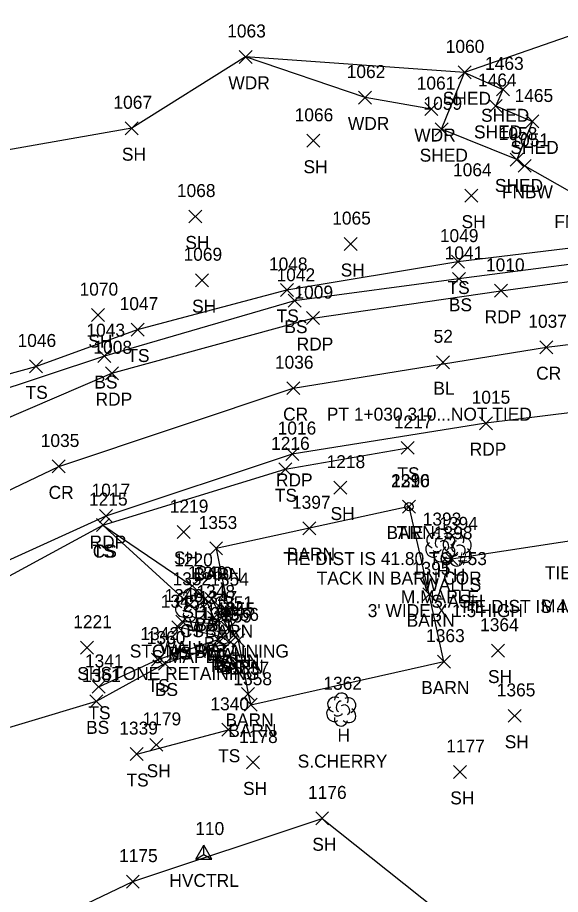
# Model space of a CAD drawing. Extents: x 1526508 to 1531550, y 369926 to 373082.
# Drawn here: x 1530893.3 to 1530976.9, y 370047.9 to 370183.1 of the extents above; entities that cross this region are included whole.
import ezdxf

# ---------------------------------------------------------------- set-up
doc = ezdxf.new("R2010")
doc.units = 0
for name, color, linetype in [('C_A', 7, 'Continuous'), ('C_C', 7, 'Continuous'), ('C_I', 7, 'Continuous'), ('C_TIC', 7, 'Continuous'), ('CBP', 7, 'Continuous'), ('CPSM', 7, 'Continuous'), ('L_A', 7, 'Continuous'), ('L_C', 7, 'Continuous'), ('L_I', 7, 'Continuous'), ('L_TIC', 7, 'Continuous'), ('LAWA', 7, 'Continuous'), ('LBC', 7, 'Continuous'), ('LELB', 7, 'Continuous'), ('LFNC', 7, 'Continuous'), ('LSOGP', 7, 'Continuous'), ('LTD', 7, 'Continuous'), ('LW', 7, 'Continuous'), ('LWS', 7, 'Continuous'), ('P_A', 7, 'Continuous'), ('P_I', 7, 'Continuous'), ('P_TIC', 7, 'Continuous'), ('PET', 7, 'Continuous'), ('PRC', 7, 'Continuous')]:
    doc.layers.add(name, color=color, linetype=linetype)

msp = doc.modelspace()

# ---------------------------------------------------------------- linework, layer by layer
at = {"layer": 'C_TIC'}
for points in [[(1530957.87, 370128.95), (1530959.87, 370130.95)], [(1530959.87, 370128.95), (1530957.87, 370130.95)]]:
    msp.add_lwpolyline(points, dxfattribs=at)
at = {"layer": 'CBP'}
for radius in [0.625, 0.0833]:
    msp.add_circle((1530953.6, 370107.69), radius, dxfattribs=at)
at = {"layer": 'CPSM'}
for p, q in [((1530920.75, 370053.36), (1530922, 370055.53)), ((1530923.25, 370053.36), (1530922, 370055.53)), ((1530922, 370054.08), (1530922, 370055.53)), ((1530920.75, 370053.36), (1530922, 370054.08)), ((1530922, 370054.08), (1530922, 370054.08)), ((1530922, 370054.08), (1530923.25, 370053.36)), ((1530920.75, 370053.36), (1530923.25, 370053.36))]:
    msp.add_line(p, q, dxfattribs=at)
at = {"layer": 'L_TIC'}
for points in [[(1530927.42, 370176.02), (1530929.42, 370178.02)], [(1530929.42, 370176.02), (1530927.42, 370178.02)], [(1530961.18, 370173.64), (1530963.18, 370175.64)], [(1530963.18, 370173.64), (1530961.18, 370175.64)], [(1530967.07, 370171.02), (1530969.07, 370173.02)], [(1530969.07, 370171.02), (1530967.07, 370173.02)], [(1530945.83, 370169.76), (1530947.83, 370171.76)], [(1530947.83, 370169.76), (1530945.83, 370171.76)], [(1530956.06, 370167.98), (1530958.06, 370169.98)], [(1530958.06, 370167.98), (1530956.06, 370169.98)], [(1530965.98, 370168.46), (1530967.98, 370170.46)], [(1530967.98, 370168.46), (1530965.98, 370170.46)], [(1530971.61, 370166.07), (1530973.61, 370168.07)], [(1530973.61, 370166.07), (1530971.61, 370168.07)], [(1530909.89, 370165.02), (1530911.89, 370167.02)], [(1530911.89, 370165.02), (1530909.89, 370167.02)], [(1530957.62, 370164.87), (1530959.62, 370166.87)], [(1530959.62, 370164.87), (1530957.62, 370166.87)], [(1530937.86, 370163.09), (1530939.86, 370165.09)], [(1530939.86, 370163.09), (1530937.86, 370165.09)], [(1530969.21, 370160.2), (1530971.21, 370162.2)], [(1530971.21, 370160.2), (1530969.21, 370162.2)], [(1530970.44, 370159.23), (1530972.44, 370161.23)], [(1530972.44, 370159.23), (1530970.44, 370161.23)], [(1530962.21, 370154.62), (1530964.21, 370156.62)], [(1530964.21, 370154.62), (1530962.21, 370156.62)], [(1530919.67, 370151.42), (1530921.67, 370153.42)], [(1530921.67, 370151.42), (1530919.67, 370153.42)], [(1530943.6, 370147.17), (1530945.6, 370149.17)], [(1530945.6, 370147.17), (1530943.6, 370149.17)], [(1530960.14, 370144.47), (1530962.14, 370146.47)], [(1530962.14, 370144.47), (1530960.14, 370146.47)], [(1530920.7, 370141.6), (1530922.7, 370143.6)], [(1530922.7, 370141.6), (1530920.7, 370143.6)], [(1530960.31, 370141.81), (1530962.31, 370143.81)], [(1530962.31, 370141.81), (1530960.31, 370143.81)], [(1530933.8, 370140.1), (1530935.8, 370142.1)], [(1530935.8, 370140.1), (1530933.8, 370142.1)], [(1530934.97, 370138.44), (1530936.97, 370140.44)], [(1530936.97, 370138.44), (1530934.97, 370140.44)], [(1530904.71, 370136.22), (1530906.71, 370138.22)], [(1530906.71, 370136.22), (1530904.71, 370138.22)], [(1530910.8, 370133.99), (1530912.8, 370135.99)], [(1530912.8, 370133.99), (1530910.8, 370135.99)], [(1530905.69, 370129.9), (1530907.69, 370131.9)], [(1530907.69, 370129.9), (1530905.69, 370131.9)], [(1530895.12, 370128.31), (1530897.12, 370130.31)], [(1530897.12, 370128.31), (1530895.12, 370130.31)], [(1530952.41, 370115.76), (1530954.41, 370117.76)], [(1530954.41, 370115.76), (1530952.41, 370117.76)], [(1530933.55, 370112.45), (1530935.55, 370114.45)], [(1530935.55, 370112.45), (1530933.55, 370114.45)], [(1530942.04, 370109.63), (1530944.04, 370111.63)], [(1530944.04, 370109.63), (1530942.04, 370111.63)], [(1530952.62, 370106.71), (1530954.62, 370108.71)], [(1530954.62, 370106.71), (1530952.62, 370108.71)], [(1530905.44, 370103.85), (1530907.44, 370105.85)], [(1530907.44, 370103.85), (1530905.44, 370105.85)], [(1530905.44, 370103.85), (1530907.44, 370105.85)], [(1530907.44, 370103.85), (1530905.44, 370105.85)], [(1530937.27, 370103.37), (1530939.27, 370105.37)], [(1530939.27, 370103.37), (1530937.27, 370105.37)], [(1530917.89, 370102.78), (1530919.89, 370104.78)], [(1530919.89, 370102.78), (1530917.89, 370104.78)], [(1530922.9, 370100.25), (1530924.9, 370102.25)], [(1530924.9, 370100.25), (1530922.9, 370102.25)], [(1530959.13, 370098.67), (1530961.13, 370100.67)], [(1530961.13, 370098.67), (1530959.13, 370100.67)], [(1530919.21, 370094.49), (1530921.21, 370096.49)], [(1530921.21, 370094.49), (1530919.21, 370096.49)], [(1530921.25, 370092.52), (1530923.25, 370094.52)], [(1530923.25, 370092.52), (1530921.25, 370094.52)], [(1530922.2, 370092.44), (1530924.2, 370094.44)], [(1530924.2, 370092.44), (1530922.2, 370094.44)], [(1530955.74, 370093.19), (1530957.74, 370095.19)], [(1530957.74, 370093.19), (1530955.74, 370095.19)], [(1530918.87, 370091.58), (1530920.87, 370093.58)], [(1530920.87, 370091.58), (1530918.87, 370093.58)], [(1530924.67, 370091.52), (1530926.67, 370093.52)], [(1530926.67, 370091.52), (1530924.67, 370093.52)], [(1530922.55, 370089.61), (1530924.55, 370091.61)], [(1530924.55, 370089.61), (1530922.55, 370091.61)], [(1530917.06, 370088.11), (1530919.06, 370090.11)], [(1530919.06, 370088.11), (1530917.06, 370090.11)], [(1530917.69, 370088.99), (1530919.69, 370090.99)], [(1530919.69, 370088.99), (1530917.69, 370090.99)], [(1530922.86, 370088.69), (1530924.86, 370090.69)], [(1530924.86, 370088.69), (1530922.86, 370090.69)], [(1530924.77, 370087.89), (1530926.77, 370089.89)], [(1530926.77, 370087.89), (1530924.77, 370089.89)], [(1530925.63, 370086.93), (1530927.63, 370088.93)], [(1530927.63, 370086.93), (1530925.63, 370088.93)], [(1530923.22, 370086.21), (1530925.22, 370088.21)], [(1530925.22, 370086.21), (1530923.22, 370088.21)], [(1530924.06, 370086.54), (1530926.06, 370088.54)], [(1530926.06, 370086.54), (1530924.06, 370088.54)], [(1530925.15, 370085.84), (1530927.15, 370087.84)], [(1530927.15, 370085.84), (1530925.15, 370087.84)], [(1530926.29, 370086.09), (1530928.29, 370088.09)], [(1530928.29, 370086.09), (1530926.29, 370088.09)], [(1530903, 370084.96), (1530905, 370086.96)], [(1530905, 370084.96), (1530903, 370086.96)], [(1530966.3, 370084.5), (1530968.3, 370086.5)], [(1530968.3, 370084.5), (1530966.3, 370086.5)], [(1530913.91, 370083.12), (1530915.91, 370085.12)], [(1530915.91, 370083.12), (1530913.91, 370085.12)], [(1530957.98, 370082.81), (1530959.98, 370084.81)], [(1530959.98, 370082.81), (1530957.98, 370084.81)], [(1530915.02, 370082.51), (1530917.02, 370084.51)], [(1530917.02, 370082.51), (1530915.02, 370084.51)], [(1530904.8, 370078.92), (1530906.8, 370080.92)], [(1530906.8, 370078.92), (1530904.8, 370080.92)], [(1530927.82, 370077.82), (1530929.82, 370079.82)], [(1530929.82, 370077.82), (1530927.82, 370079.82)], [(1530904.42, 370076.67), (1530906.42, 370078.67)], [(1530906.42, 370076.67), (1530904.42, 370078.67)], [(1530928.24, 370076.17), (1530930.24, 370078.17)], [(1530930.24, 370076.17), (1530928.24, 370078.17)], [(1530968.87, 370074.45), (1530970.87, 370076.45)], [(1530970.87, 370074.45), (1530968.87, 370076.45)], [(1530924.79, 370072.3), (1530926.79, 370074.3)], [(1530926.79, 370072.3), (1530924.79, 370074.3)], [(1530913.7, 370069.98), (1530915.7, 370071.98)], [(1530915.7, 370069.98), (1530913.7, 370071.98)], [(1530910.67, 370068.56), (1530912.67, 370070.56)], [(1530912.67, 370068.56), (1530910.67, 370070.56)], [(1530928.55, 370067.26), (1530930.55, 370069.26)], [(1530930.55, 370067.26), (1530928.55, 370069.26)], [(1530960.47, 370065.8), (1530962.47, 370067.8)], [(1530962.47, 370065.8), (1530960.47, 370067.8)], [(1530939.23, 370058.65), (1530941.23, 370060.65)], [(1530941.23, 370058.65), (1530939.23, 370060.65)], [(1530910.06, 370048.9), (1530912.06, 370050.9)], [(1530912.06, 370048.9), (1530910.06, 370050.9)]]:
    msp.add_lwpolyline(points, dxfattribs=at)
at = {"layer": 'LAWA'}
msp.add_lwpolyline([(1530957.06, 370168.98), (1530946.83, 370170.76), (1530928.42, 370177.02)], dxfattribs=at)
at = {"layer": 'LBC'}
for points in [[(1530970.21, 370161.2), (1530958.62, 370165.87), (1530962.18, 370174.64), (1530968.07, 370172.02), (1530966.98, 370169.46), (1530972.61, 370167.07)], [(1530972.61, 370167.07), (1530970.21, 370161.2)], [(1530956.74, 370094.19), (1530953.62, 370107.71), (1530938.27, 370104.37)], [(1530938.27, 370104.37), (1530923.9, 370101.25)], [(1530923.9, 370101.25), (1530925.67, 370092.52), (1530926.63, 370087.93), (1530927.29, 370087.09), (1530928.82, 370078.82), (1530929.24, 370077.17), (1530958.98, 370083.81)], [(1530958.98, 370083.81), (1530956.74, 370094.19)]]:
    msp.add_lwpolyline(points, dxfattribs=at)
at = {"layer": 'LELB'}
for points in [[(1530883.54, 370125.84), (1530896.12, 370129.31), (1530911.8, 370134.99), (1530934.8, 370141.1), (1530961.14, 370145.47), (1530991.24, 370149.13)], [(1530991.34, 370146.7), (1530961.31, 370142.81), (1530935.97, 370139.44), (1530906.69, 370130.9), (1530888.23, 370124.76)], [(1530685.88, 369975.28), (1530717.44, 369995.35), (1530750.55, 370015.24), (1530789.81, 370037.94), (1530822.42, 370057.69), (1530849.78, 370074.39), (1530878.97, 370089.95), (1530906.44, 370104.85), (1530934.55, 370113.45), (1530953.41, 370116.76)], [(1530906.44, 370104.85), (1530919.87, 370092.58)], [(1530906.44, 370104.85), (1530920.21, 370095.49)], [(1530923.55, 370090.61), (1530922.25, 370093.52)], [(1530925.06, 370087.54), (1530918.06, 370089.11)], [(1530926.15, 370086.84), (1530916.02, 370083.51), (1530905.42, 370077.67)], [(1530905.8, 370079.92), (1530914.91, 370084.12), (1530924.22, 370087.21)], [(1530905.42, 370077.67), (1530882.45, 370070.8)], [(1530911.67, 370069.56), (1530925.79, 370073.3)]]:
    msp.add_lwpolyline(points, dxfattribs=at)
at = {"layer": 'LFNC'}
msp.add_lwpolyline([(1530971.44, 370160.23), (1530979.51, 370155.65), (1530990.48, 370153.17), (1530994.12, 370164.89), (1530997.54, 370173.36)], dxfattribs=at)
at = {"layer": 'LSOGP'}
for points in [[(1530986.53, 370183.09), (1530962.18, 370174.64), (1530928.42, 370177.02), (1530910.89, 370166.02), (1530884.86, 370161.48), (1530871.57, 370167.13), (1530872.93, 370160.21), (1530842.14, 370150.83), (1530839.93, 370155.57), (1530813.18, 370149.48)], [(1530823.4, 370012.81), (1530854.24, 370024.39), (1530880.41, 370035.27), (1530911.06, 370049.9), (1530940.23, 370059.65), (1530968.16, 370037.39), (1530982.37, 370020.77)]]:
    msp.add_lwpolyline(points, dxfattribs=at)
at = {"layer": 'LTD'}
for p, q in [((1530958.41, 370101.78), (1530958.41, 370101.78)), ((1530958.41, 370101.78), (1530958.41, 370101.78)), ((1530960.95, 370101.12), (1530960.95, 370101.12)), ((1530960.95, 370101.12), (1530960.95, 370101.12)), ((1530919.87, 370092.58), (1530919.87, 370092.58)), ((1530919.87, 370092.58), (1530919.87, 370092.58)), ((1530943.15, 370076.47), (1530943.15, 370076.47)), ((1530943.15, 370076.47), (1530943.15, 370076.47))]:
    msp.add_line(p, q, dxfattribs=at)
for centre in [(1530958.46, 370103.22), (1530961, 370102.56), (1530919.92, 370094.02), (1530943.2, 370077.9)]:
    msp.add_arc(centre, 1.05, 335.5272, 180.9563, dxfattribs=at)
for centre, major_axis, ratio, start_param, end_param in [((1530957.62, 370102.45), (1.21, -0.51), 0.895232, 1.570796, 4.712389), ((1530959.45, 370102.37), (-1.14, -0.48), 0.949671, 1.570796, 4.712389), ((1530958.2, 370102.24), (-0.208, -0.792), 0.645439, 3.141593, 6.283185), ((1530958.91, 370101.62), (-0.5, 0.667), 0.989748, 3.141593, 6.283185), ((1530960.16, 370101.79), (1.21, -0.51), 0.895232, 1.570796, 4.712389), ((1530960.74, 370101.58), (-0.208, -0.792), 0.645439, 3.141593, 6.283185), ((1530961.99, 370101.71), (-1.14, -0.48), 0.949671, 1.570796, 4.712389), ((1530957.33, 370101.08), (0.58, -1.04), 0.959034, 3.141593, 6.283185), ((1530957.95, 370101.03), (-0.625, -0.083), 0.423636, 0, 3.141593), ((1530959.87, 370100.41), (0.58, -1.04), 0.959034, 3.141593, 6.283185), ((1530959.41, 370100.95), (-1.09, 0.79), 0.841452, 1.570796, 4.712389), ((1530961.45, 370100.95), (-0.5, 0.667), 0.989748, 3.141593, 6.283185), ((1530961.95, 370100.29), (-1.09, 0.79), 0.841452, 1.570796, 4.712389), ((1530958.41, 370100.28), (0.26, 1.06), 0.942809, 1.570796, 4.712389), ((1530960.95, 370099.62), (0.26, 1.06), 0.942809, 1.570796, 4.712389), ((1530960.49, 370100.37), (-0.625, -0.083), 0.423636, 0, 3.141593), ((1530919.08, 370093.25), (1.21, -0.51), 0.895232, 1.570796, 4.712389), ((1530920.91, 370093.17), (-1.14, -0.48), 0.949671, 1.570796, 4.712389), ((1530918.79, 370091.87), (0.58, -1.04), 0.959034, 3.141593, 6.283185), ((1530919.66, 370093.04), (-0.208, -0.792), 0.645439, 3.141593, 6.283185), ((1530920.37, 370092.42), (-0.5, 0.667), 0.989748, 3.141593, 6.283185), ((1530919.41, 370091.83), (-0.625, -0.083), 0.423636, 0, 3.141593), ((1530920.87, 370091.75), (-1.09, 0.79), 0.841452, 1.570796, 4.712389), ((1530919.87, 370091.08), (0.26, 1.06), 0.942809, 1.570796, 4.712389), ((1530942.36, 370077.13), (1.21, -0.51), 0.895232, 1.570796, 4.712389), ((1530944.19, 370077.05), (-1.14, -0.48), 0.949671, 1.570796, 4.712389), ((1530942.07, 370075.76), (0.58, -1.04), 0.959034, 3.141593, 6.283185), ((1530942.94, 370076.92), (-0.208, -0.792), 0.645439, 3.141593, 6.283185), ((1530943.65, 370076.3), (-0.5, 0.667), 0.989748, 3.141593, 6.283185), ((1530942.69, 370075.72), (-0.625, -0.083), 0.423636, 0, 3.141593), ((1530944.15, 370075.63), (-1.09, 0.79), 0.841452, 1.570796, 4.712389), ((1530943.15, 370074.97), (0.26, 1.06), 0.942809, 1.570796, 4.712389)]:
    msp.add_ellipse(centre, major_axis=major_axis, ratio=ratio, start_param=start_param, end_param=end_param, dxfattribs=at)
at = {"layer": 'LW'}
for points in [[(1530923.2, 370093.44), (1530925.77, 370088.89)], [(1530918.69, 370089.99), (1530923.86, 370089.69)]]:
    msp.add_lwpolyline(points, dxfattribs=at)
at = {"layer": 'LWS'}
msp.add_lwpolyline([(1530960.13, 370099.67), (1530989.37, 370104.12)], dxfattribs=at)
at = {"layer": 'P_TIC'}
for points in [[(1530966.77, 370139.97), (1530968.77, 370141.97)], [(1530968.77, 370139.97), (1530966.77, 370141.97)], [(1530937.81, 370135.76), (1530939.81, 370137.76)], [(1530939.81, 370135.76), (1530937.81, 370137.76)], [(1530973.77, 370131.27), (1530975.77, 370133.27)], [(1530975.77, 370131.27), (1530973.77, 370133.27)], [(1530906.84, 370127.26), (1530908.84, 370129.26)], [(1530908.84, 370127.26), (1530906.84, 370129.26)], [(1530934.78, 370124.96), (1530936.78, 370126.96)], [(1530936.78, 370124.96), (1530934.78, 370126.96)], [(1530964.47, 370119.56), (1530966.47, 370121.56)], [(1530966.47, 370119.56), (1530964.47, 370121.56)], [(1530934.63, 370114.81), (1530936.63, 370116.81)], [(1530936.63, 370114.81), (1530934.63, 370116.81)], [(1530898.64, 370112.89), (1530900.64, 370114.89)], [(1530900.64, 370112.89), (1530898.64, 370114.89)], [(1530905.91, 370105.24), (1530907.91, 370107.24)], [(1530907.91, 370105.24), (1530905.91, 370107.24)]]:
    msp.add_lwpolyline(points, dxfattribs=at)
at = {"layer": 'PET'}
for points in [[(1530659.86, 369987.59), (1530689.68, 370004.88), (1530725.77, 370025.63), (1530760.95, 370046.59), (1530789.35, 370063.64), (1530821.52, 370083.59), (1530847.47, 370098.66), (1530877.57, 370115.25), (1530907.84, 370128.26), (1530938.81, 370136.76), (1530967.77, 370140.97), (1531005.44, 370146.08), (1531034.99, 370150.93)], [(1531038.44, 370130.38), (1531006.6, 370125.67), (1530965.47, 370120.56), (1530935.63, 370115.81), (1530906.91, 370106.24), (1530877.46, 370092.89), (1530855.5, 370080.74), (1530824.98, 370062.43), (1530800.48, 370048.15), (1530769.96, 370030.14), (1530741.1, 370012.79), (1530710.76, 369994.53), (1530684.03, 369978.66), (1530669.6, 369970.09)]]:
    msp.add_lwpolyline(points, dxfattribs=at)
at = {"layer": 'PRC'}
msp.add_lwpolyline([(1530664.43, 369978.53), (1530688.65, 369992.9), (1530715.76, 370008.79), (1530744.4, 370025.81), (1530774.39, 370044.32), (1530799.13, 370059.29), (1530828.47, 370076.59), (1530863.72, 370096.73), (1530899.64, 370113.89), (1530935.78, 370125.96), (1530974.77, 370132.27), (1531009.67, 370136.56), (1531036.22, 370140.48)], dxfattribs=at)

# ---------------------------------------------------------------- texts
at = {"layer": 'C_A'}
for s, p in [('BL', (1530957.36, 370124.95)), ('TIE', (1530951.68, 370102.69)), ('HVCTRL', (1530916.69, 370049.08))]:
    msp.add_text(s, height=2, dxfattribs=at).set_placement(p)
at = {"layer": 'C_C'}
for s, p in [('PT 1+030.310...NOT TIED', (1530940.95, 370120.95)), ('TIE DIST IS 41.80 TO #53', (1530934.25, 370098.69)), ('TIE DIST IS 31.35 TO #53', (1530974.54, 370096.51)), ('TACK IN BARN COR', (1530939.39, 370095.69)), ('TIE DIST IS 41.56 TO #53', (1530961.35, 370091.32))]:
    msp.add_text(s, height=2, dxfattribs=at).set_placement(p)
at = {"layer": 'C_I'}
for s, p in [('52', (1530957.4, 370132.95)), ('2210', (1530950.83, 370110.69)), ('110', (1530920.68, 370057.08))]:
    msp.add_text(s, height=2, dxfattribs=at).set_placement(p)
at = {"layer": 'L_A'}
for s, p in [('WDR', (1530925.78, 370172.02)), ('SHED', (1530958.81, 370169.64)), ('SHED', (1530964.71, 370167.02)), ('WDR', (1530944.19, 370165.76)), ('WDR', (1530954.42, 370163.98)), ('SHED', (1530963.62, 370164.46)), ('SHED', (1530969.24, 370162.07)), ('SH', (1530909.37, 370161.02)), ('SHED', (1530955.25, 370160.87)), ('SH', (1530937.35, 370159.09)), ('SHED', (1530966.84, 370156.2)), ('FNBW', (1530967.91, 370155.23)), ('SH', (1530961.7, 370150.62)), ('FNBW', (1530975.99, 370150.65)), ('SH', (1530919.15, 370147.42)), ('SH', (1530943.09, 370143.17)), ('TS', (1530959.54, 370140.47)), ('SH', (1530920.19, 370137.6)), ('BS', (1530959.75, 370137.81)), ('TS', (1530933.21, 370136.1)), ('BS', (1530934.41, 370134.44)), ('SH', (1530904.2, 370132.22)), ('TS', (1530910.21, 370129.99)), ('BS', (1530905.13, 370125.9)), ('TS', (1530894.53, 370124.31)), ('TS', (1530951.82, 370111.76)), ('TS', (1530932.95, 370108.45)), ('SH', (1530941.52, 370105.63)), ('BARN', (1530950.14, 370102.71)), ('TS', (1530904.85, 370099.85)), ('CS', (1530904.88, 370099.85)), ('BARN', (1530934.79, 370099.37)), ('SH', (1530917.38, 370098.78)), ('BARN', (1530920.41, 370096.25)), ('H', (1530957.84, 370096.78)), ('H', (1530960.38, 370096.12)), ('WALLS', (1530955.68, 370094.67)), ('SH', (1530918.7, 370090.49)), ('WALL', (1530919.69, 370088.44)), ('BS', (1530920.69, 370088.52)), ('BARN', (1530953.25, 370089.19)), ('CS', (1530918.31, 370087.58)), ('H', (1530919.31, 370087.58)), ('BARN', (1530922.18, 370087.52)), ('BS', (1530921.99, 370085.61)), ('WALL', (1530915.18, 370084.99)), ('BS', (1530916.5, 370084.11)), ('WALL', (1530920.35, 370084.69)), ('WALL', (1530922.25, 370083.89)), ('BARN', (1530923.15, 370082.93)), ('TS', (1530922.63, 370082.21)), ('BS', (1530923.5, 370082.54)), ('BARN', (1530923.8, 370082.09)), ('BS', (1530924.59, 370081.84)), ('SH', (1530902.49, 370080.96)), ('SH', (1530965.78, 370080.5)), ('TS', (1530913.32, 370079.12)), ('BARN', (1530955.49, 370078.81)), ('BS', (1530914.46, 370078.51)), ('TS', (1530904.21, 370074.92)), ('BARN', (1530925.33, 370073.82)), ('BS', (1530903.86, 370072.67)), ('BARN', (1530925.76, 370072.17)), ('H', (1530942.58, 370071.47)), ('SH', (1530968.36, 370070.45)), ('TS', (1530924.2, 370068.3)), ('SH', (1530913.19, 370065.98)), ('TS', (1530910.08, 370064.56)), ('SH', (1530928.04, 370063.26)), ('SH', (1530959.96, 370061.8)), ('SH', (1530938.71, 370054.65))]:
    msp.add_text(s, height=2, dxfattribs=at).set_placement(p)
at = {"layer": 'L_C'}
for s, p in [('M.MAPLE', (1530952.35, 370092.78)), ('S.ASH', (1530957.03, 370092.12)), ('M.MAPLE', (1530973.95, 370091.39)), ("3' WIDE X 1.5'HIGH", (1530947.25, 370090.67)), ('STONE RETAINING', (1530910.59, 370084.44)), ('S.MAPLE', (1530913.94, 370083.58)), ('STONE RETAINING', (1530906.08, 370080.99)), ('S.CHERRY', (1530936.46, 370067.47))]:
    msp.add_text(s, height=2, dxfattribs=at).set_placement(p)
at = {"layer": 'L_I'}
for s, p in [('1063', (1530925.6, 370180.02)), ('1060', (1530959.27, 370177.64)), ('1463', (1530965.33, 370175.02)), ('1062', (1530944.01, 370173.76)), ('1061', (1530954.8, 370171.98)), ('1464', (1530964.24, 370172.46)), ('1465', (1530969.87, 370170.07)), ('1067', (1530908.07, 370169.02)), ('1059', (1530955.84, 370168.87)), ('1066', (1530935.99, 370167.09)), ('1058', (1530967.43, 370164.2)), ('1051', (1530969.23, 370163.23)), ('1064', (1530960.39, 370158.62)), ('1068', (1530917.85, 370155.42)), ('1065', (1530941.78, 370151.17)), ('1049', (1530958.36, 370148.47)), ('1069', (1530918.87, 370145.6)), ('1041', (1530959.1, 370145.81)), ('1048', (1530932.03, 370144.1)), ('1042', (1530933.2, 370142.44)), ('1070', (1530902.85, 370140.22)), ('1047', (1530909.03, 370137.99)), ('1043', (1530903.91, 370133.9)), ('1046', (1530893.3, 370132.31)), ('1217', (1530951.28, 370119.76)), ('1216', (1530932.36, 370116.45)), ('1218', (1530940.91, 370113.63)), ('1396', (1530950.88, 370110.71)), ('1215', (1530904.31, 370107.85)), ('1215', (1530904.31, 370107.85)), ('1397', (1530935.58, 370107.37)), ('1219', (1530916.75, 370106.78)), ('1393', (1530955.72, 370104.78)), ('1353', (1530921.2, 370104.25)), ('1394', (1530958.26, 370104.12)), ('1398', (1530957.44, 370102.67)), ('1220', (1530917.43, 370098.49)), ('1349', (1530919.55, 370096.52)), ('1350', (1530920.42, 370096.44)), ('1395', (1530954.05, 370097.19)), ('1352', (1530917.18, 370095.58)), ('1352', (1530917.18, 370095.58)), ('1354', (1530922.98, 370095.52)), ('1348', (1530920.86, 370093.61)), ('1346', (1530915.94, 370092.99)), ('1347', (1530921.17, 370092.69)), ('1345', (1530915.37, 370092.11)), ('1351', (1530923.64, 370091.89)), ('1355', (1530923.94, 370090.93)), ('1343', (1530921.53, 370090.21)), ('1344', (1530922.37, 370090.54)), ('1359', (1530923.45, 370089.84)), ('1356', (1530924.54, 370090.09)), ('1221', (1530901.88, 370088.96)), ('1364', (1530964.56, 370088.5)), ('1342', (1530912.22, 370087.12)), ('1363', (1530956.24, 370086.81)), ('1360', (1530913.2, 370086.51)), ('1341', (1530903.68, 370082.92)), ('1357', (1530926.12, 370081.82)), ('1361', (1530903.25, 370080.67)), ('1358', (1530926.55, 370080.17)), ('1362', (1530940.41, 370079.47)), ('1365', (1530967.13, 370078.45)), ('1340', (1530923.01, 370076.3)), ('1179', (1530912.56, 370073.98)), ('1339', (1530908.97, 370072.56)), ('1178', (1530927.43, 370071.26)), ('1177', (1530959.34, 370069.8)), ('1176', (1530938.05, 370062.65)), ('1175', (1530908.94, 370052.9))]:
    msp.add_text(s, height=2, dxfattribs=at).set_placement(p)
at = {"layer": 'P_A'}
for s, p in [('RDP', (1530965.25, 370135.97)), ('RDP', (1530936.3, 370131.76)), ('CR', (1530973.2, 370127.27)), ('RDP', (1530905.32, 370123.26)), ('CR', (1530934.21, 370120.96)), ('RDP', (1530962.96, 370115.56)), ('RDP', (1530933.11, 370110.81)), ('CR', (1530898.08, 370108.89)), ('RDP', (1530904.4, 370101.24))]:
    msp.add_text(s, height=2, dxfattribs=at).set_placement(p)
at = {"layer": 'P_I'}
for s, p in [('1010', (1530965.47, 370143.97)), ('1009', (1530935.96, 370139.76)), ('1037', (1530971.99, 370135.27)), ('1008', (1530904.99, 370131.26)), ('1036', (1530932.95, 370128.96)), ('1015', (1530963.26, 370123.56)), ('1016', (1530933.37, 370118.81)), ('1035', (1530896.87, 370116.89)), ('1017', (1530904.7, 370109.24))]:
    msp.add_text(s, height=2, dxfattribs=at).set_placement(p)

doc.saveas('drawing.dxf')
